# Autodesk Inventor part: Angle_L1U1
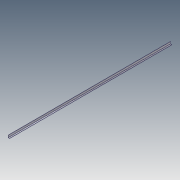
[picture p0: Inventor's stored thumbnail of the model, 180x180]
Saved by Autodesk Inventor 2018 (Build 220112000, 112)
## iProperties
Created: 2018-02
Part Number: Angle_L1U1
Material: Steel, Mild
Document SubType Name: Modeling
Designer: STK
Density: 7.85 g/cm^3
Appearance: Opal
Author: STK
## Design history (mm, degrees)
sketch "Sketch1"
  geometry: L1 (12.378, 13.448)-(12.378, 140.448); L2 (21.319, 127.804)-(21.319, 35.8); L3 (88.634, 22.389)-(34.73, 22.389); L4 (101.278, 13.448)-(12.378, 13.448); A1 r 13.411 centre (7.907, 127.804) between (21.319, 127.804) and (12.378, 140.448); A2 r 13.411 centre (34.73, 35.8) between (21.319, 35.8) and (34.73, 22.389); A3 r 13.411 centre (88.634, 8.977) between (101.278, 13.448) and (88.634, 22.389)
  constraints: 8 end point, 6 point on circle, 4 tangent, 3 centre point, 2 equal radius, 1 parallel, 1 perpendicular
  dimensions: "d5" = 13.4112 radius of A2 (derived); "d3" = 88.9 distance from line of L4.start L1 (derived); "d6" = 127 distance from line of L1.end L4 (derived); "d1" = 8.9408 distance between parallel lines of L3 L4 (derived); "d0" = 8.9408 distance between parallel lines of L2 L1 (= d1)
feature "Angle_unequal:1" sketch "Sketch1"
body "Solid1"
